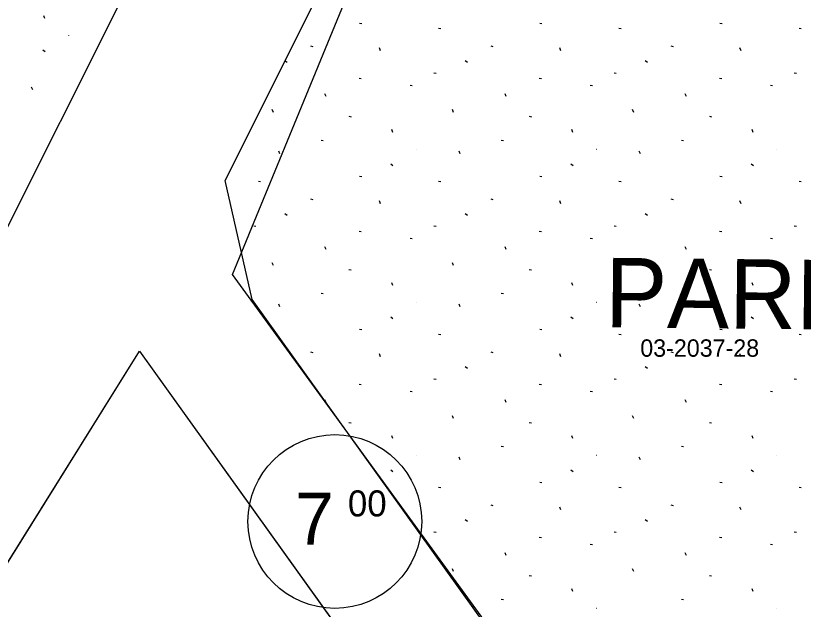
# Model space of a CAD drawing. Extents: x 413946 to 415528, y 4453939 to 4454944.
# Drawn here: x 414158.83 to 414204.14, y 4454394.09 to 4454428.25 of the extents above; entities that cross this region are included whole.
import ezdxf

# ---------------------------------------------------------------- set-up
doc = ezdxf.new("R2010")
doc.units = 0
for name, color, linetype in [('0_KADASTRO', 7, 'Continuous'), ('Level 28', 7, 'Continuous'), ('Level 33', 7, 'Continuous'), ('Level 41', 7, 'Continuous'), ('Level 54', 7, 'Continuous'), ('SEMBOL', 7, 'Continuous')]:
    doc.layers.add(name, color=color, linetype=linetype)

msp = doc.modelspace()

# ---------------------------------------------------------------- linework, layer by layer
at = {"layer": '0_KADASTRO'}
for points in [[(414171.31, 4454413.36), (414183.07, 4454442), (414206.93, 4454433.98), (414230.64, 4454426.01), (414230.44, 4454425.59), (414230.371, 4454425.45), (414226.09, 4454416.74), (414221.64, 4454407.87), (414217.44, 4454398.74), (414213.33, 4454389.73), (414209.245, 4454381.65), (414205.21, 4454373.66), (414187.97, 4454390.46)], [(414135.52, 4454360.16), (414165.95, 4454408.94), (414184.66, 4454382.84), (414190.49, 4454374.72), (414202.15, 4454367.32), (414200.03, 4454362.84), (414195.73, 4454353.76), (414191.45, 4454344.73), (414187.14, 4454335.91), (414182.75, 4454326.9), (414178.69, 4454317.76), (414172.62, 4454304.1), (414159.21, 4454324.36)]]:
    msp.add_lwpolyline(points, close=True, dxfattribs=at)
at = {"layer": 'Level 28'}
for p, q in [((414172.73, 4454444.765), (414156.409, 4454412.223)), ((414170.876, 4454418.762), (414182.5, 4454441.938)), ((414172.432, 4454411.913), (414170.876, 4454418.762)), ((414195.386, 4454379.904), (414172.432, 4454411.913)), ((414135.52, 4454360.16), (414165.95, 4454408.94)), ((414165.95, 4454408.94), (414190.49, 4454374.72))]:
    msp.add_line(p, q, dxfattribs=at)
at = {"layer": 'Level 41'}
for p, q in [((414160.505, 4454428.084), (414160.441, 4454428.245)), ((414160.505, 4454428.084), (414160.441, 4454428.245)), ((414178.615, 4454427.828), (414178.741, 4454427.804)), ((414178.615, 4454427.828), (414178.741, 4454427.804)), ((414188.983, 4454427.828), (414189.109, 4454427.804)), ((414188.983, 4454427.828), (414189.109, 4454427.804)), ((414199.351, 4454427.828), (414199.477, 4454427.804)), ((414199.351, 4454427.828), (414199.477, 4454427.804)), ((414183.163, 4454427.534), (414183.289, 4454427.511)), ((414183.163, 4454427.534), (414183.289, 4454427.511)), ((414193.531, 4454427.534), (414193.657, 4454427.511)), ((414193.531, 4454427.534), (414193.657, 4454427.511)), ((414203.899, 4454427.534), (414204.025, 4454427.511)), ((414203.899, 4454427.534), (414204.025, 4454427.511)), ((414161.863, 4454427.12), (414161.871, 4454427.119)), ((414161.863, 4454427.12), (414161.871, 4454427.119)), ((414160.388, 4454426.281), (414160.515, 4454426.183)), ((414160.388, 4454426.281), (414160.515, 4454426.183)), ((414175.795, 4454426.51), (414175.92, 4454426.485)), ((414175.795, 4454426.51), (414175.92, 4454426.485)), ((414179.828, 4454426.23), (414179.763, 4454426.393)), ((414179.828, 4454426.23), (414179.763, 4454426.393)), ((414186.163, 4454426.51), (414186.288, 4454426.485)), ((414186.163, 4454426.51), (414186.288, 4454426.485)), ((414190.196, 4454426.23), (414190.131, 4454426.393)), ((414190.196, 4454426.23), (414190.131, 4454426.393)), ((414196.531, 4454426.51), (414196.656, 4454426.485)), ((414196.531, 4454426.51), (414196.656, 4454426.485)), ((414200.564, 4454426.23), (414200.499, 4454426.393)), ((414200.564, 4454426.23), (414200.499, 4454426.393)), ((414174.335, 4454425.66), (414174.447, 4454425.573)), ((414174.335, 4454425.66), (414174.447, 4454425.573)), ((414184.688, 4454425.672), (414184.815, 4454425.573)), ((414184.688, 4454425.672), (414184.815, 4454425.573)), ((414195.056, 4454425.672), (414195.183, 4454425.573)), ((414195.056, 4454425.672), (414195.183, 4454425.573)), ((414182.893, 4454424.966), (414183.019, 4454424.943)), ((414182.893, 4454424.966), (414183.019, 4454424.943)), ((414193.261, 4454424.966), (414193.387, 4454424.943)), ((414193.261, 4454424.966), (414193.387, 4454424.943)), ((414203.629, 4454424.966), (414203.755, 4454424.943)), ((414203.629, 4454424.966), (414203.755, 4454424.943)), ((414178.588, 4454424.662), (414178.714, 4454424.639)), ((414178.588, 4454424.662), (414178.714, 4454424.639)), ((414188.956, 4454424.662), (414189.082, 4454424.639)), ((414188.956, 4454424.662), (414189.082, 4454424.639)), ((414199.324, 4454424.662), (414199.45, 4454424.639)), ((414199.324, 4454424.662), (414199.45, 4454424.639)), ((414159.807, 4454423.979), (414159.742, 4454424.141)), ((414159.807, 4454423.979), (414159.742, 4454424.141)), ((414181.517, 4454424.253), (414181.643, 4454424.228)), ((414181.517, 4454424.253), (414181.643, 4454424.228)), ((414191.885, 4454424.253), (414192.011, 4454424.228)), ((414191.885, 4454424.253), (414192.011, 4454424.228)), ((414202.253, 4454424.253), (414202.379, 4454424.228)), ((414202.253, 4454424.253), (414202.379, 4454424.228)), ((414176.685, 4454423.593), (414176.619, 4454423.756)), ((414176.685, 4454423.593), (414176.619, 4454423.756)), ((414187.053, 4454423.593), (414186.987, 4454423.756)), ((414187.053, 4454423.593), (414186.987, 4454423.756)), ((414197.421, 4454423.593), (414197.355, 4454423.756)), ((414197.421, 4454423.593), (414197.355, 4454423.756)), ((414173.654, 4454422.679), (414173.589, 4454422.842)), ((414173.654, 4454422.679), (414173.589, 4454422.842)), ((414184.022, 4454422.679), (414183.957, 4454422.842)), ((414184.022, 4454422.679), (414183.957, 4454422.842)), ((414194.39, 4454422.679), (414194.325, 4454422.842)), ((414194.39, 4454422.679), (414194.325, 4454422.842)), ((414178.004, 4454422.458), (414178.13, 4454422.435)), ((414178.004, 4454422.458), (414178.13, 4454422.435)), ((414188.372, 4454422.458), (414188.498, 4454422.435)), ((414188.372, 4454422.458), (414188.498, 4454422.435)), ((414198.74, 4454422.458), (414198.866, 4454422.435)), ((414198.74, 4454422.458), (414198.866, 4454422.435)), ((414180.526, 4454421.529), (414180.462, 4454421.691)), ((414180.526, 4454421.529), (414180.462, 4454421.691)), ((414190.894, 4454421.529), (414190.83, 4454421.691)), ((414190.894, 4454421.529), (414190.83, 4454421.691)), ((414201.262, 4454421.529), (414201.198, 4454421.691)), ((414201.262, 4454421.529), (414201.198, 4454421.691)), ((414176.4, 4454421.091), (414176.526, 4454421.066)), ((414176.4, 4454421.091), (414176.526, 4454421.066)), ((414186.768, 4454421.091), (414186.894, 4454421.066)), ((414186.768, 4454421.091), (414186.894, 4454421.066)), ((414197.136, 4454421.091), (414197.262, 4454421.066)), ((414197.136, 4454421.091), (414197.262, 4454421.066)), ((414174.035, 4454420.296), (414173.97, 4454420.458)), ((414174.035, 4454420.296), (414173.97, 4454420.458)), ((414181.884, 4454420.566), (414181.892, 4454420.564)), ((414181.884, 4454420.566), (414181.892, 4454420.564)), ((414184.403, 4454420.296), (414184.338, 4454420.458)), ((414184.403, 4454420.296), (414184.338, 4454420.458)), ((414192.252, 4454420.566), (414192.26, 4454420.564)), ((414192.252, 4454420.566), (414192.26, 4454420.564)), ((414194.771, 4454420.296), (414194.706, 4454420.458)), ((414194.771, 4454420.296), (414194.706, 4454420.458)), ((414202.62, 4454420.566), (414202.628, 4454420.564)), ((414202.62, 4454420.566), (414202.628, 4454420.564)), ((414180.409, 4454419.727), (414180.536, 4454419.628)), ((414180.409, 4454419.727), (414180.536, 4454419.628)), ((414190.777, 4454419.727), (414190.904, 4454419.628)), ((414190.777, 4454419.727), (414190.904, 4454419.628)), ((414201.145, 4454419.727), (414201.272, 4454419.628)), ((414201.145, 4454419.727), (414201.272, 4454419.628)), ((414178.615, 4454419.022), (414178.741, 4454418.998)), ((414178.615, 4454419.022), (414178.741, 4454418.998)), ((414188.983, 4454419.022), (414189.109, 4454418.998)), ((414188.983, 4454419.022), (414189.109, 4454418.998)), ((414199.351, 4454419.022), (414199.477, 4454418.998)), ((414199.351, 4454419.022), (414199.477, 4454418.998)), ((414172.795, 4454418.728), (414172.921, 4454418.705)), ((414172.795, 4454418.728), (414172.921, 4454418.705)), ((414183.163, 4454418.728), (414183.289, 4454418.705)), ((414183.163, 4454418.728), (414183.289, 4454418.705)), ((414193.531, 4454418.728), (414193.657, 4454418.705)), ((414193.531, 4454418.728), (414193.657, 4454418.705)), ((414203.899, 4454418.728), (414204.025, 4454418.705)), ((414203.899, 4454418.728), (414204.025, 4454418.705)), ((414175.795, 4454417.704), (414175.92, 4454417.679)), ((414175.795, 4454417.704), (414175.92, 4454417.679)), ((414186.163, 4454417.704), (414186.288, 4454417.679)), ((414186.163, 4454417.704), (414186.288, 4454417.679)), ((414196.531, 4454417.704), (414196.656, 4454417.679)), ((414196.531, 4454417.704), (414196.656, 4454417.679)), ((414179.828, 4454417.424), (414179.763, 4454417.587)), ((414179.828, 4454417.424), (414179.763, 4454417.587)), ((414190.196, 4454417.424), (414190.131, 4454417.587)), ((414190.196, 4454417.424), (414190.131, 4454417.587)), ((414200.564, 4454417.424), (414200.499, 4454417.587)), ((414200.564, 4454417.424), (414200.499, 4454417.587)), ((414174.32, 4454416.866), (414174.447, 4454416.767)), ((414174.32, 4454416.866), (414174.447, 4454416.767)), ((414184.688, 4454416.866), (414184.815, 4454416.767)), ((414184.688, 4454416.866), (414184.815, 4454416.767)), ((414195.056, 4454416.866), (414195.183, 4454416.767)), ((414195.056, 4454416.866), (414195.183, 4454416.767)), ((414172.525, 4454416.16), (414172.651, 4454416.137)), ((414172.525, 4454416.16), (414172.651, 4454416.137)), ((414178.588, 4454415.856), (414178.714, 4454415.833)), ((414178.588, 4454415.856), (414178.714, 4454415.833)), ((414182.893, 4454416.16), (414183.019, 4454416.137)), ((414182.893, 4454416.16), (414183.019, 4454416.137)), ((414188.956, 4454415.856), (414189.082, 4454415.833)), ((414188.956, 4454415.856), (414189.082, 4454415.833)), ((414193.261, 4454416.16), (414193.387, 4454416.137)), ((414193.261, 4454416.16), (414193.387, 4454416.137)), ((414199.324, 4454415.856), (414199.45, 4454415.833)), ((414199.324, 4454415.856), (414199.45, 4454415.833)), ((414203.629, 4454416.16), (414203.755, 4454416.137)), ((414203.629, 4454416.16), (414203.755, 4454416.137)), ((414181.517, 4454415.447), (414181.643, 4454415.422)), ((414181.517, 4454415.447), (414181.643, 4454415.422)), ((414191.885, 4454415.447), (414192.011, 4454415.422)), ((414191.885, 4454415.447), (414192.011, 4454415.422)), ((414202.253, 4454415.447), (414202.379, 4454415.422)), ((414202.253, 4454415.447), (414202.379, 4454415.422)), ((414176.685, 4454414.787), (414176.619, 4454414.95)), ((414176.685, 4454414.787), (414176.619, 4454414.95)), ((414187.053, 4454414.787), (414186.987, 4454414.95)), ((414187.053, 4454414.787), (414186.987, 4454414.95)), ((414197.421, 4454414.787), (414197.355, 4454414.95)), ((414197.421, 4454414.787), (414197.355, 4454414.95)), ((414173.654, 4454413.873), (414173.589, 4454414.036)), ((414173.654, 4454413.873), (414173.589, 4454414.036)), ((414184.022, 4454413.873), (414183.957, 4454414.036)), ((414184.022, 4454413.873), (414183.957, 4454414.036)), ((414194.39, 4454413.873), (414194.325, 4454414.036)), ((414194.39, 4454413.873), (414194.325, 4454414.036)), ((414178.004, 4454413.652), (414178.13, 4454413.629)), ((414178.004, 4454413.652), (414178.13, 4454413.629)), ((414188.372, 4454413.652), (414188.498, 4454413.629)), ((414188.372, 4454413.652), (414188.498, 4454413.629)), ((414198.74, 4454413.652), (414198.866, 4454413.629)), ((414198.74, 4454413.652), (414198.866, 4454413.629)), ((414180.526, 4454412.723), (414180.462, 4454412.885)), ((414180.526, 4454412.723), (414180.462, 4454412.885)), ((414190.894, 4454412.723), (414190.83, 4454412.885)), ((414190.894, 4454412.723), (414190.83, 4454412.885)), ((414201.262, 4454412.723), (414201.198, 4454412.885)), ((414201.262, 4454412.723), (414201.198, 4454412.885)), ((414176.4, 4454412.285), (414176.526, 4454412.26)), ((414176.4, 4454412.285), (414176.526, 4454412.26)), ((414186.768, 4454412.285), (414186.894, 4454412.26)), ((414186.768, 4454412.285), (414186.894, 4454412.26)), ((414197.136, 4454412.285), (414197.262, 4454412.26)), ((414197.136, 4454412.285), (414197.262, 4454412.26)), ((414181.884, 4454411.76), (414181.892, 4454411.758)), ((414181.884, 4454411.76), (414181.892, 4454411.758)), ((414192.252, 4454411.76), (414192.26, 4454411.758)), ((414192.252, 4454411.76), (414192.26, 4454411.758)), ((414202.62, 4454411.76), (414202.628, 4454411.758)), ((414202.62, 4454411.76), (414202.628, 4454411.758)), ((414174.035, 4454411.49), (414173.97, 4454411.652)), ((414174.035, 4454411.49), (414173.97, 4454411.652)), ((414184.403, 4454411.49), (414184.338, 4454411.652)), ((414184.403, 4454411.49), (414184.338, 4454411.652)), ((414194.771, 4454411.49), (414194.706, 4454411.652)), ((414194.771, 4454411.49), (414194.706, 4454411.652)), ((414180.409, 4454410.921), (414180.536, 4454410.822)), ((414180.409, 4454410.921), (414180.536, 4454410.822)), ((414190.777, 4454410.921), (414190.904, 4454410.822)), ((414190.777, 4454410.921), (414190.904, 4454410.822)), ((414201.145, 4454410.921), (414201.272, 4454410.822)), ((414201.145, 4454410.921), (414201.272, 4454410.822)), ((414178.615, 4454410.216), (414178.741, 4454410.192)), ((414178.615, 4454410.216), (414178.741, 4454410.192)), ((414183.163, 4454409.922), (414183.289, 4454409.899)), ((414183.163, 4454409.922), (414183.289, 4454409.899)), ((414188.983, 4454410.216), (414189.109, 4454410.192)), ((414188.983, 4454410.216), (414189.109, 4454410.192)), ((414193.531, 4454409.922), (414193.657, 4454409.899)), ((414193.531, 4454409.922), (414193.657, 4454409.899)), ((414199.351, 4454410.216), (414199.477, 4454410.192)), ((414199.351, 4454410.216), (414199.477, 4454410.192)), ((414203.899, 4454409.922), (414204.025, 4454409.899)), ((414203.899, 4454409.922), (414204.025, 4454409.899)), ((414175.795, 4454408.898), (414175.92, 4454408.873)), ((414175.795, 4454408.898), (414175.92, 4454408.873)), ((414179.828, 4454408.618), (414179.763, 4454408.781)), ((414179.828, 4454408.618), (414179.763, 4454408.781)), ((414186.163, 4454408.898), (414186.288, 4454408.873)), ((414186.163, 4454408.898), (414186.288, 4454408.873)), ((414190.196, 4454408.618), (414190.131, 4454408.781)), ((414190.196, 4454408.618), (414190.131, 4454408.781)), ((414196.531, 4454408.898), (414196.656, 4454408.873)), ((414196.531, 4454408.898), (414196.656, 4454408.873)), ((414200.564, 4454408.618), (414200.499, 4454408.781)), ((414200.564, 4454408.618), (414200.499, 4454408.781)), ((414184.688, 4454408.06), (414184.815, 4454407.961)), ((414184.688, 4454408.06), (414184.815, 4454407.961)), ((414195.056, 4454408.06), (414195.183, 4454407.961)), ((414195.056, 4454408.06), (414195.183, 4454407.961)), ((414182.893, 4454407.354), (414183.019, 4454407.331)), ((414182.893, 4454407.354), (414183.019, 4454407.331)), ((414193.261, 4454407.354), (414193.387, 4454407.331)), ((414193.261, 4454407.354), (414193.387, 4454407.331)), ((414203.629, 4454407.354), (414203.755, 4454407.331)), ((414203.629, 4454407.354), (414203.755, 4454407.331)), ((414178.588, 4454407.05), (414178.714, 4454407.027)), ((414178.588, 4454407.05), (414178.714, 4454407.027)), ((414188.956, 4454407.05), (414189.082, 4454407.027)), ((414188.956, 4454407.05), (414189.082, 4454407.027)), ((414199.324, 4454407.05), (414199.45, 4454407.027)), ((414199.324, 4454407.05), (414199.45, 4454407.027)), ((414181.517, 4454406.641), (414181.643, 4454406.616)), ((414181.517, 4454406.641), (414181.643, 4454406.616)), ((414191.885, 4454406.641), (414192.011, 4454406.616)), ((414191.885, 4454406.641), (414192.011, 4454406.616)), ((414202.253, 4454406.641), (414202.379, 4454406.616)), ((414202.253, 4454406.641), (414202.379, 4454406.616)), ((414176.684, 4454405.984), (414176.619, 4454406.144)), ((414176.684, 4454405.984), (414176.619, 4454406.144)), ((414187.053, 4454405.981), (414186.987, 4454406.144)), ((414187.053, 4454405.981), (414186.987, 4454406.144)), ((414197.421, 4454405.981), (414197.355, 4454406.144)), ((414197.421, 4454405.981), (414197.355, 4454406.144)), ((414184.022, 4454405.067), (414183.957, 4454405.23)), ((414184.022, 4454405.067), (414183.957, 4454405.23)), ((414194.39, 4454405.067), (414194.325, 4454405.23)), ((414194.39, 4454405.067), (414194.325, 4454405.23)), ((414178.004, 4454404.846), (414178.13, 4454404.823)), ((414178.004, 4454404.846), (414178.13, 4454404.823)), ((414188.372, 4454404.846), (414188.498, 4454404.823)), ((414188.372, 4454404.846), (414188.498, 4454404.823)), ((414198.74, 4454404.846), (414198.866, 4454404.823)), ((414198.74, 4454404.846), (414198.866, 4454404.823)), ((414180.526, 4454403.917), (414180.462, 4454404.079)), ((414180.526, 4454403.917), (414180.462, 4454404.079)), ((414190.894, 4454403.917), (414190.83, 4454404.079)), ((414190.894, 4454403.917), (414190.83, 4454404.079)), ((414201.262, 4454403.917), (414201.198, 4454404.079)), ((414201.262, 4454403.917), (414201.198, 4454404.079)), ((414186.768, 4454403.479), (414186.894, 4454403.454)), ((414186.768, 4454403.479), (414186.894, 4454403.454)), ((414197.136, 4454403.479), (414197.262, 4454403.454)), ((414197.136, 4454403.479), (414197.262, 4454403.454)), ((414181.884, 4454402.954), (414181.892, 4454402.952)), ((414181.884, 4454402.954), (414181.892, 4454402.952)), ((414184.403, 4454402.684), (414184.338, 4454402.846)), ((414184.403, 4454402.684), (414184.338, 4454402.846)), ((414192.252, 4454402.954), (414192.26, 4454402.952)), ((414192.252, 4454402.954), (414192.26, 4454402.952)), ((414194.771, 4454402.684), (414194.706, 4454402.846)), ((414194.771, 4454402.684), (414194.706, 4454402.846)), ((414202.62, 4454402.954), (414202.628, 4454402.952)), ((414202.62, 4454402.954), (414202.628, 4454402.952)), ((414180.409, 4454402.115), (414180.536, 4454402.016)), ((414180.409, 4454402.115), (414180.536, 4454402.016)), ((414190.777, 4454402.115), (414190.904, 4454402.016)), ((414190.777, 4454402.115), (414190.904, 4454402.016)), ((414201.145, 4454402.115), (414201.272, 4454402.016)), ((414201.145, 4454402.115), (414201.272, 4454402.016)), ((414188.983, 4454401.41), (414189.109, 4454401.386)), ((414188.983, 4454401.41), (414189.109, 4454401.386)), ((414199.351, 4454401.41), (414199.477, 4454401.386)), ((414199.351, 4454401.41), (414199.477, 4454401.386)), ((414183.163, 4454401.116), (414183.289, 4454401.093)), ((414183.163, 4454401.116), (414183.289, 4454401.093)), ((414193.531, 4454401.116), (414193.657, 4454401.093)), ((414193.531, 4454401.116), (414193.657, 4454401.093)), ((414203.899, 4454401.116), (414204.025, 4454401.093)), ((414203.899, 4454401.116), (414204.025, 4454401.093)), ((414186.163, 4454400.092), (414186.288, 4454400.067)), ((414186.163, 4454400.092), (414186.288, 4454400.067)), ((414190.196, 4454399.812), (414190.131, 4454399.975)), ((414190.196, 4454399.812), (414190.131, 4454399.975)), ((414196.531, 4454400.092), (414196.656, 4454400.067)), ((414196.531, 4454400.092), (414196.656, 4454400.067)), ((414200.564, 4454399.812), (414200.499, 4454399.975)), ((414200.564, 4454399.812), (414200.499, 4454399.975)), ((414184.688, 4454399.254), (414184.815, 4454399.155)), ((414184.688, 4454399.254), (414184.815, 4454399.155)), ((414195.056, 4454399.254), (414195.183, 4454399.155)), ((414195.056, 4454399.254), (414195.183, 4454399.155)), ((414182.893, 4454398.548), (414183.019, 4454398.525)), ((414182.893, 4454398.548), (414183.019, 4454398.525)), ((414188.956, 4454398.244), (414189.082, 4454398.221)), ((414188.956, 4454398.244), (414189.082, 4454398.221)), ((414193.261, 4454398.548), (414193.387, 4454398.525)), ((414193.261, 4454398.548), (414193.387, 4454398.525)), ((414199.324, 4454398.244), (414199.45, 4454398.221)), ((414199.324, 4454398.244), (414199.45, 4454398.221)), ((414203.629, 4454398.548), (414203.755, 4454398.525)), ((414203.629, 4454398.548), (414203.755, 4454398.525)), ((414191.885, 4454397.835), (414192.011, 4454397.81)), ((414191.885, 4454397.835), (414192.011, 4454397.81)), ((414202.253, 4454397.835), (414202.379, 4454397.81)), ((414202.253, 4454397.835), (414202.379, 4454397.81)), ((414187.053, 4454397.175), (414186.987, 4454397.338)), ((414187.053, 4454397.175), (414186.987, 4454397.338)), ((414197.421, 4454397.175), (414197.355, 4454397.338)), ((414197.421, 4454397.175), (414197.355, 4454397.338)), ((414184.022, 4454396.261), (414183.957, 4454396.424)), ((414184.022, 4454396.261), (414183.957, 4454396.424)), ((414194.39, 4454396.261), (414194.325, 4454396.424)), ((414194.39, 4454396.261), (414194.325, 4454396.424)), ((414188.372, 4454396.04), (414188.498, 4454396.017)), ((414188.372, 4454396.04), (414188.498, 4454396.017)), ((414198.74, 4454396.04), (414198.866, 4454396.017)), ((414198.74, 4454396.04), (414198.866, 4454396.017)), ((414190.894, 4454395.111), (414190.83, 4454395.273)), ((414190.894, 4454395.111), (414190.83, 4454395.273)), ((414201.262, 4454395.111), (414201.198, 4454395.273)), ((414201.262, 4454395.111), (414201.198, 4454395.273)), ((414186.768, 4454394.673), (414186.894, 4454394.648)), ((414186.768, 4454394.673), (414186.894, 4454394.648)), ((414197.136, 4454394.673), (414197.262, 4454394.648)), ((414197.136, 4454394.673), (414197.262, 4454394.648)), ((414192.252, 4454394.148), (414192.26, 4454394.146)), ((414192.252, 4454394.148), (414192.26, 4454394.146)), ((414202.62, 4454394.148), (414202.628, 4454394.146)), ((414202.62, 4454394.148), (414202.628, 4454394.146))]:
    msp.add_line(p, q, dxfattribs=at)
at = {"layer": 'Level 54'}
msp.add_lwpolyline([(414190.49, 4454374.72), (414202.15, 4454367.32), (414200.03, 4454362.84), (414195.73, 4454353.76), (414191.45, 4454344.73), (414187.14, 4454335.91), (414182.75, 4454326.9), (414178.69, 4454317.76), (414172.482, 4454303.789), (414135.52, 4454360.16), (414165.95, 4454408.94)], close=True, dxfattribs=at)
at = {"layer": 'SEMBOL'}
msp.add_circle((414177.193, 4454399.142), 5, dxfattribs=at)

# ---------------------------------------------------------------- texts
at = {"layer": '0_KADASTRO'}
msp.add_text('03-2037-28', height=1, dxfattribs=at).set_placement((414194.765, 4454408.623))
at = {"layer": 'Level 33'}
msp.add_text('PARK', height=4, rotation=359.4136, dxfattribs=at).set_placement((414192.727, 4454410.32))
at = {"layer": 'SEMBOL'}
for s, height, p in [('00', 1.5, (414177.942, 4454399.432)), ('7', 3, (414174.897, 4454397.802))]:
    msp.add_text(s, height=height, dxfattribs=at).set_placement(p)

doc.saveas('drawing.dxf')
